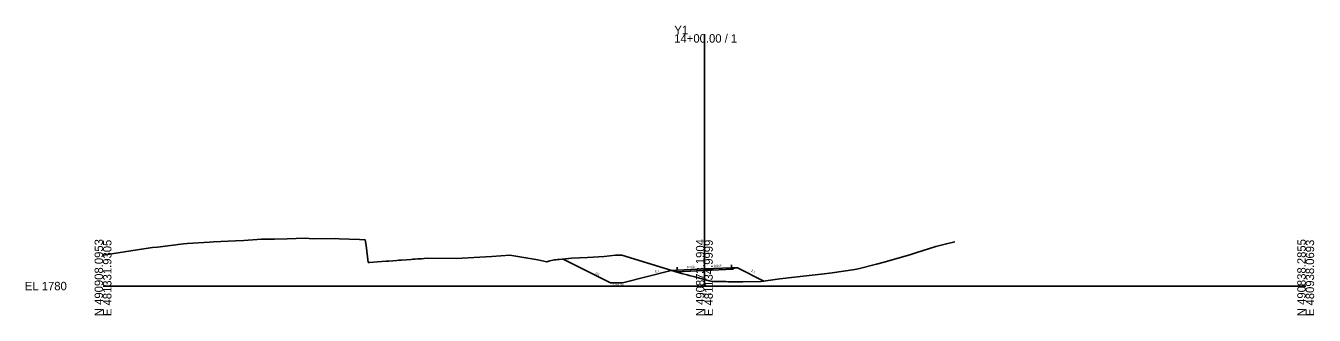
# Model space of a CAD drawing. Extents: x -26 to 403, y -10 to 6561.
# Drawn here: x -25.7 to 402.8, y 3990.3 to 4086.5 of the extents above; entities that cross this region are included whole.
import ezdxf

# ---------------------------------------------------------------- set-up
doc = ezdxf.new("R2010")
doc.units = 0
for name, color, linetype in [('Exist Cross Section Cell', 7, 'Continuous'), ('Exist XS Center Line Elevation Label', 7, 'Continuous'), ('Exist XS Ground Line', 7, 'Continuous'), ('Prop Road Sect_ Boring - Header (ID Tx)', 7, 'Continuous'), ('Prop Road Sect_ Material - Tx (Composite Desc)', 7, 'Continuous'), ('Prop XS Ditch Slope Text', 7, 'Continuous'), ('Prop XS Ditch Standard Text', 7, 'Continuous'), ('Prop XS EOT Tick Mark', 7, 'Continuous'), ('Prop XS Finish Grade', 7, 'Continuous'), ('Prop XS Finish Grade Earthwork', 7, 'Continuous'), ('Prop XS Finish Grade Pavement', 7, 'Continuous'), ('Prop XS Pvmt Edge Slope', 7, 'Continuous'), ('Prop XS SE Text', 7, 'Continuous'), ('Prop XS Side Slope Text', 7, 'Continuous'), ('Prop XS Subgrade Earthwork', 7, 'Continuous')]:
    doc.layers.add(name, color=color, linetype=linetype)

msp = doc.modelspace()

# ---------------------------------------------------------------- linework, layer by layer
at = {"layer": 'Exist Cross Section Cell'}
for p, q in [((200, 4000), (200, 4083.7)), ((0, 4000), (200, 4000)), ((200, 4000), (400, 4000))]:
    msp.add_line(p, q, dxfattribs=at)
at = {"layer": 'Exist XS Ground Line'}
msp.add_lwpolyline([(0, 4010.23), (12.77, 4012.23), (16.41, 4012.76), (18.15, 4012.97), (26.78, 4014.05), (27.98, 4014.13), (35.41, 4014.57), (36.72, 4014.71), (44.03, 4015.08), (46.88, 4015.17), (52.66, 4015.56), (57.04, 4015.61), (61.29, 4015.71), (67.19, 4015.86), (69.92, 4015.68), (77.35, 4015.79), (78.55, 4015.74), (85.29, 4015.48), (87.18, 4015.41), (87.51, 4013.44), (88.23, 4007.84), (88.6, 4007.86), (91.19, 4008.05), (94.16, 4008.26), (95.06, 4008.32), (97.75, 4008.52), (98.39, 4008.56), (99.29, 4008.63), (100.97, 4008.75), (102.44, 4008.85), (103.03, 4008.9), (103.83, 4008.95), (104.72, 4009.02), (105.1, 4009.04), (105.88, 4009.1), (106.86, 4009.17), (107.86, 4009.24), (117.48, 4009.11), (129.29, 4009.8), (135.26, 4010.22), (144.66, 4008.67), (147.58, 4008.04), (148.6, 4008.36), (149.66, 4008.63), (150.12, 4008.68), (150.61, 4008.71), (151.15, 4008.77), (151.73, 4008.81), (155.79, 4009.25), (161.08, 4009.54), (166.68, 4009.84), (170.43, 4010.21), (170.83, 4010.22), (171.54, 4010.21), (171.89, 4010.22), (172.5, 4010.21), (192.35, 4004.22), (194.33, 4003.69), (194.92, 4003.53), (196.83, 4003.01), (197.58, 4002.81), (200, 4002.16), (201.62, 4001.73), (202.21, 4001.57), (203, 4001.56), (207.14, 4001.53), (207.91, 4001.44), (212.77, 4001.44), (218.86, 4001.52), (225.13, 4002.42), (233.86, 4003.43), (239.88, 4004.08), (242.49, 4004.35), (250.04, 4005.48), (251.12, 4005.72), (257.22, 4007.3), (259.75, 4007.94), (260.19, 4008.06), (268.37, 4010.39), (270.35, 4011.01), (277, 4013.12), (280.51, 4014.05), (283.28, 4014.7)], dxfattribs=at)
at = {"layer": 'Prop Road Sect_ Boring - Header (ID Tx)'}
for points in [[(191, 4005.25), (190.43, 4004.68), (189.91, 4005.2)], [(209, 4006.09), (210, 4006.05), (209.52, 4005.57)]]:
    msp.add_lwpolyline(points, close=True, dxfattribs=at)
at = {"layer": 'Prop Road Sect_ Material - Tx (Composite Desc)'}
for points in [[(189, 4005.16), (189.2, 4005.17), (172.5, 4010.21), (171.89, 4010.22), (171.54, 4010.21), (170.83, 4010.22), (170.43, 4010.21), (166.68, 4009.84), (161.08, 4009.54), (155.79, 4009.25), (153.05, 4008.95), (168.76, 4001.1), (172.76, 4001.1)], [(189.2, 4005.17), (189.91, 4005.2), (190.27, 4004.85)], [(190.43, 4004.68), (190.27, 4004.85), (190.76, 4004.7)], [(202.21, 4001.57), (203, 4001.56), (207.14, 4001.53), (207.91, 4001.44), (212.77, 4001.44), (218.86, 4001.52), (219.73, 4001.64), (211, 4006.01), (210, 4006.05), (209.52, 4005.57), (200.03, 4005.13), (190.76, 4004.7), (192.35, 4004.22), (194.33, 4003.69), (194.92, 4003.53), (196.83, 4003.01), (197.58, 4002.81), (200, 4002.16), (201.62, 4001.73)]]:
    msp.add_lwpolyline(points, close=True, dxfattribs=at)
at = {"layer": 'Prop XS EOT Tick Mark'}
for p, q in [((209, 4006.09), (209, 4007.09)), ((191, 4005.25), (191, 4006.25))]:
    msp.add_line(p, q, dxfattribs=at)
at = {"layer": 'Prop XS Finish Grade'}
for p, q in [((191, 4005.25), (189.91, 4005.2)), ((209, 4006.09), (210, 4006.05))]:
    msp.add_line(p, q, dxfattribs=at)
at = {"layer": 'Prop XS Finish Grade Earthwork'}
for p, q in [((168.76, 4001.1), (153.05, 4008.95)), ((189, 4005.16), (172.76, 4001.1)), ((189, 4005.16), (189.91, 4005.2)), ((210, 4006.05), (211, 4006.01)), ((211, 4006.01), (219.73, 4001.64)), ((172.76, 4001.1), (168.76, 4001.1))]:
    msp.add_line(p, q, dxfattribs=at)
at = {"layer": 'Prop XS Finish Grade Pavement'}
for p, q in [((191, 4005.25), (200, 4005.67)), ((200, 4005.67), (209, 4006.09))]:
    msp.add_line(p, q, dxfattribs=at)
at = {"layer": 'Prop XS Pvmt Edge Slope'}
for p, q in [((191, 4005.25), (190.43, 4004.68)), ((209, 4006.09), (209.52, 4005.57))]:
    msp.add_line(p, q, dxfattribs=at)
at = {"layer": 'Prop XS Subgrade Earthwork'}
for p, q in [((190.43, 4004.68), (189.91, 4005.2)), ((190.43, 4004.68), (200.03, 4005.13)), ((200.03, 4005.13), (209.52, 4005.57)), ((210, 4006.05), (209.52, 4005.57))]:
    msp.add_line(p, q, dxfattribs=at)

# ---------------------------------------------------------------- texts
at = {"layer": 'Exist Cross Section Cell'}
for s, p in [('Y1', (190, 4083.7)), ('14+00.00 / 1', (190, 4080.9)), ('EL 1780', (-26, 3998.6))]:
    msp.add_text(s, height=2.8, dxfattribs=at).set_placement(p)
for s, p in [('N 490908.0953', (0, 3990)), ('N 490873.1904', (200, 3990)), ('N 490838.2855', (400, 3990)), ('E 481331.9305', (2.8, 3990)), ('E 481134.9999', (202.8, 3990)), ('E 480938.0693', (402.8, 3990))]:
    msp.add_text(s, height=2.8, rotation=90, dxfattribs=at).set_placement(p)
at = {"layer": 'Exist XS Center Line Elevation Label'}
msp.add_text('1782.16', height=0.75, dxfattribs=at).set_placement((198.47, 3996.98))
at = {"layer": 'Prop XS Ditch Slope Text'}
msp.add_text('4:1', height=0.75, rotation=14.0362, dxfattribs=at).set_placement((183.6, 4004.38))
at = {"layer": 'Prop XS Ditch Standard Text'}
msp.add_text('1781.10', height=0.75, dxfattribs=at).set_placement((169.39, 3999.98))
at = {"layer": 'Prop XS SE Text'}
for p in [(203.17, 4006.32), (194.17, 4005.9)]:
    msp.add_text('0.046', height=0.75, rotation=2.649, dxfattribs=at).set_placement(p)
at = {"layer": 'Prop XS Side Slope Text'}
for p in [(163.69, 4004.08), (215.49, 4004.86)]:
    msp.add_text('2:1', height=0.75, rotation=333.4349, dxfattribs=at).set_placement(p)

doc.saveas('drawing.dxf')
